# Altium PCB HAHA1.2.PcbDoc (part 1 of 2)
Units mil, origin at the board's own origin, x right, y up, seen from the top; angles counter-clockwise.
Board outline 7003.97 x 7003.97 mil, 2 copper layers (Top Layer, Bottom Layer); 140 components, 182 nets, 713 pads, 299 vias.
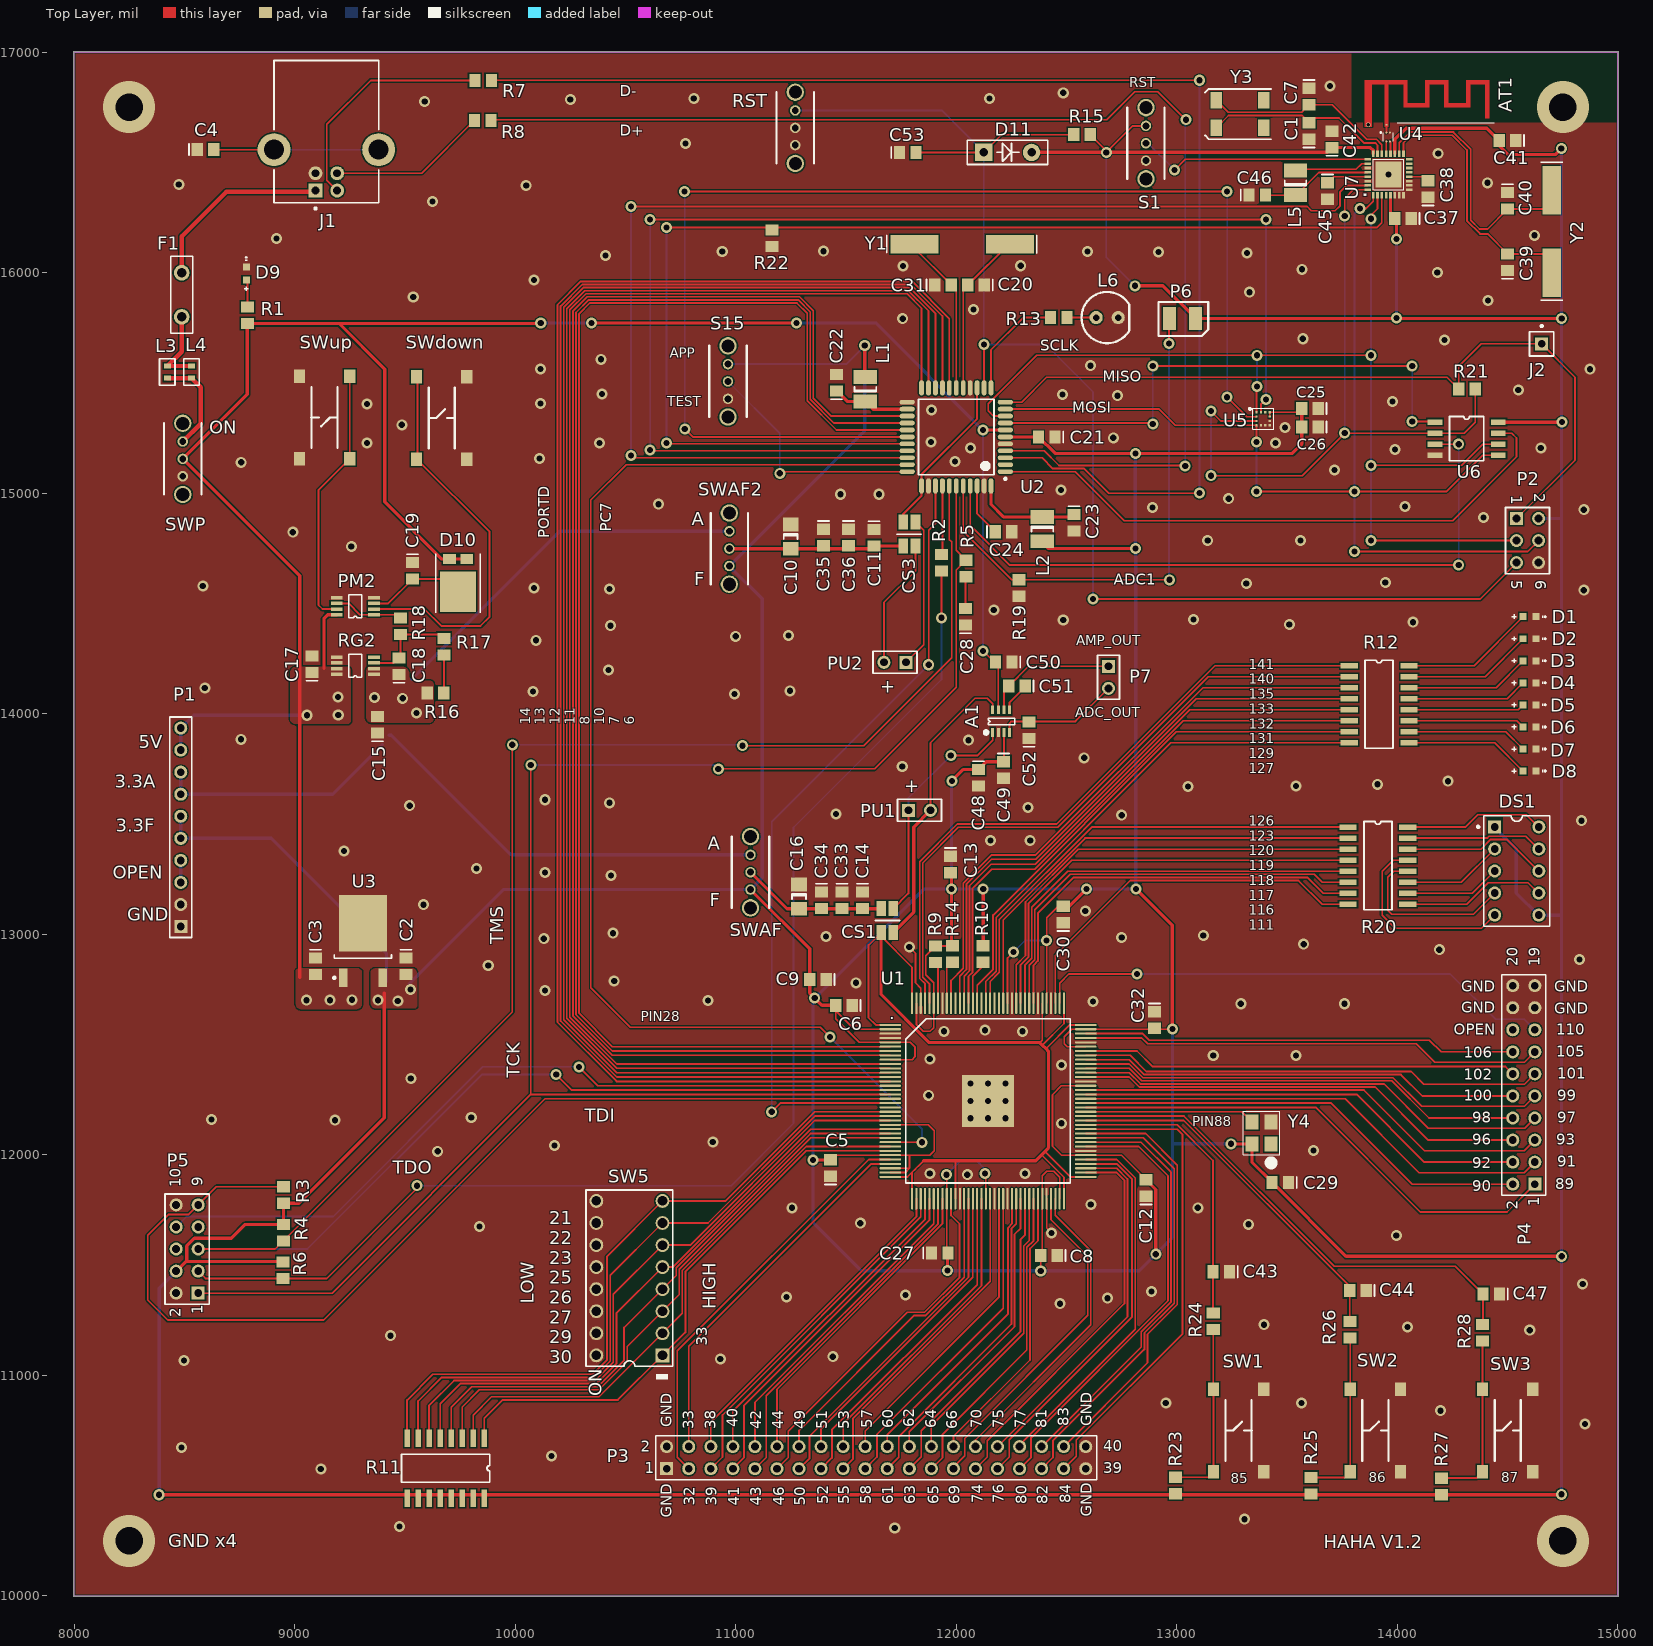
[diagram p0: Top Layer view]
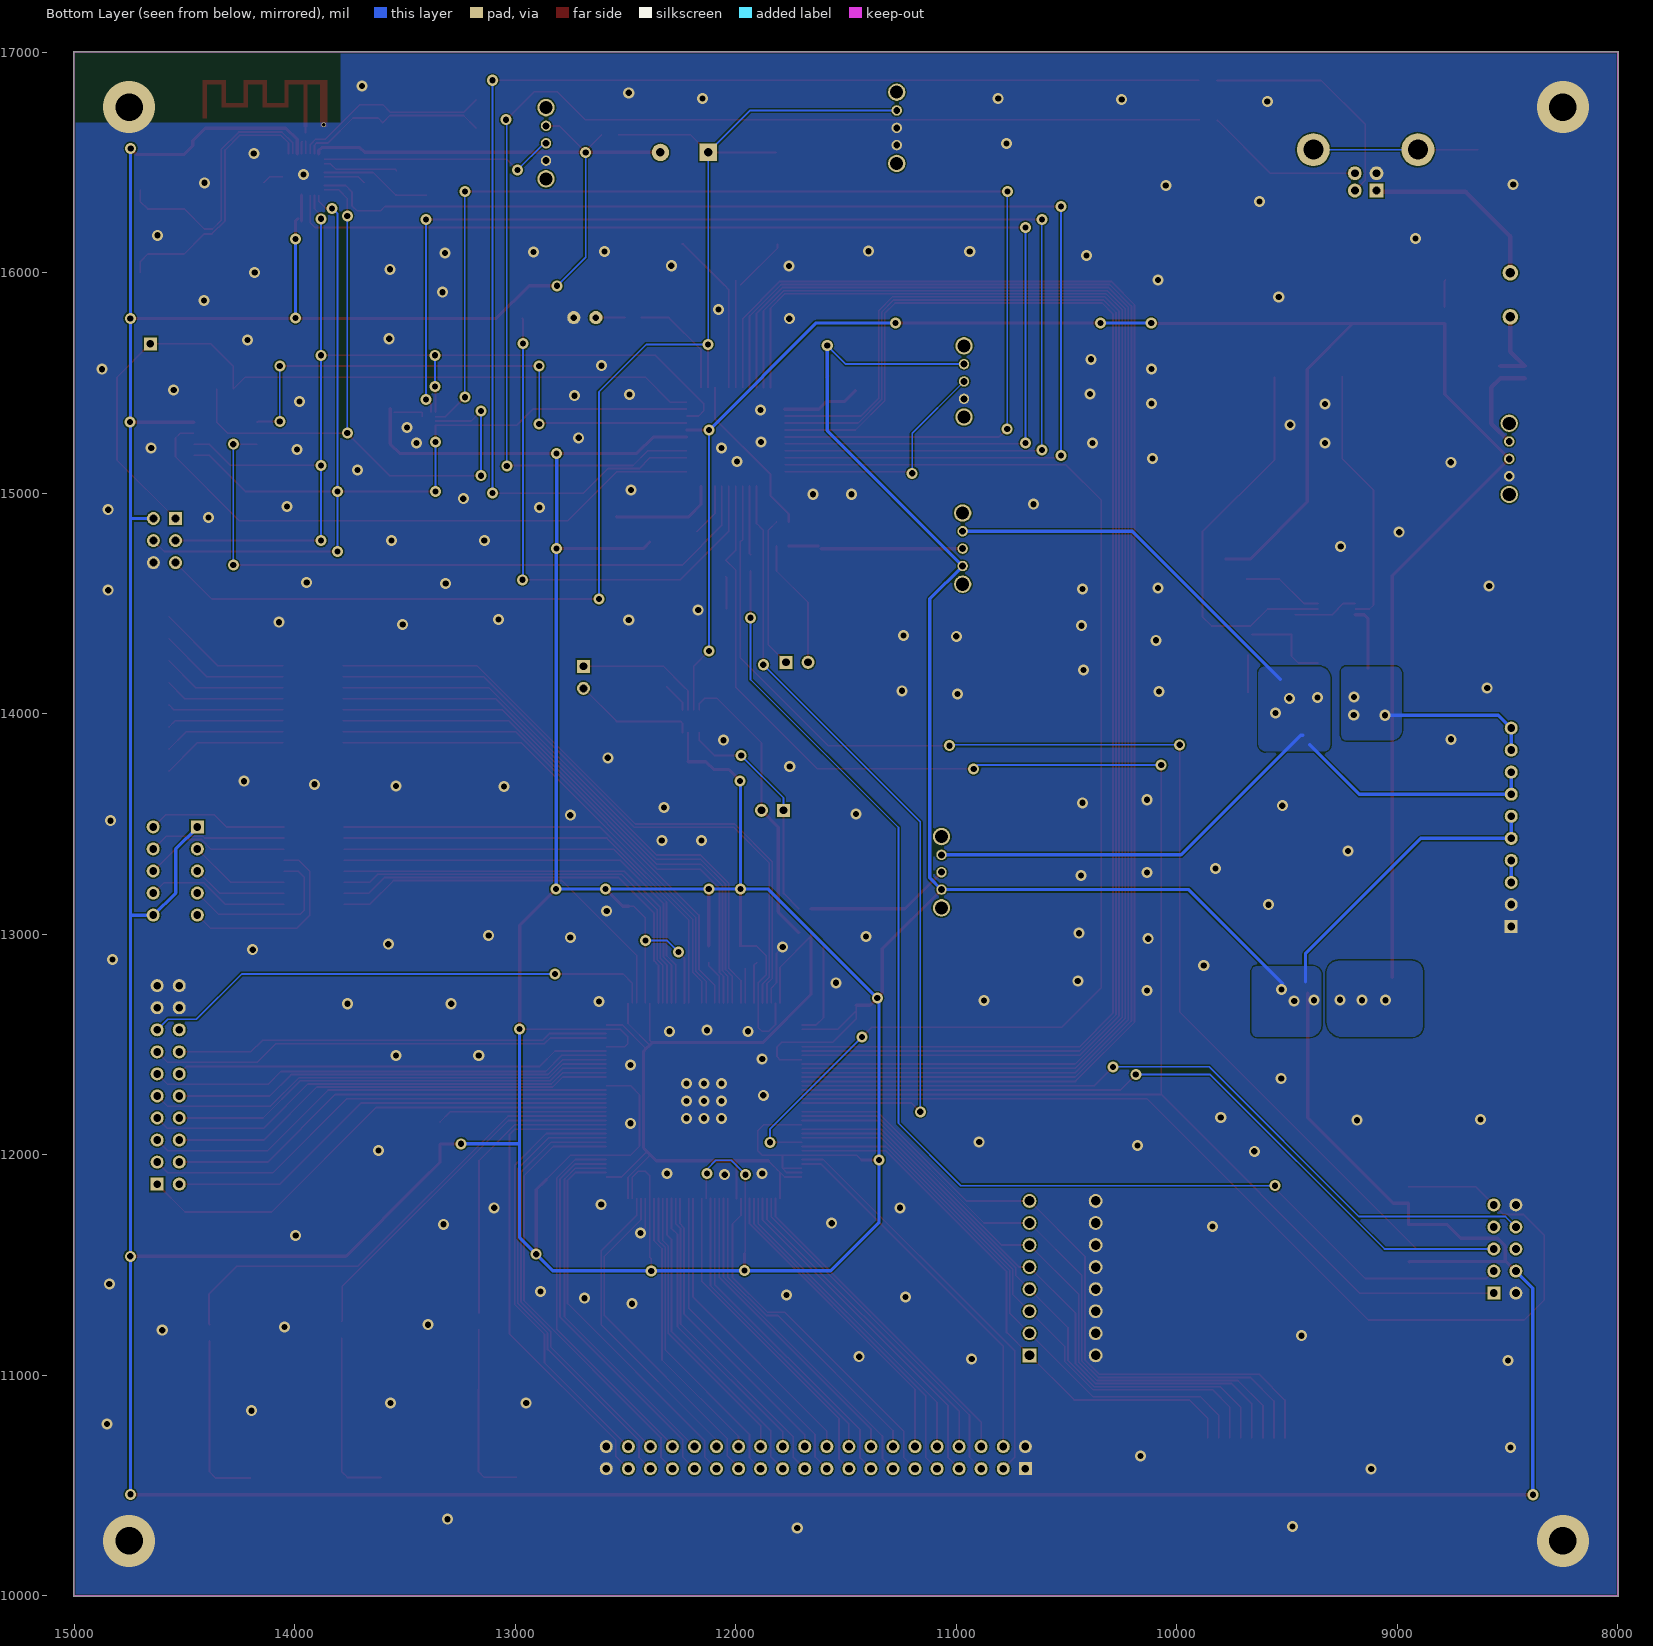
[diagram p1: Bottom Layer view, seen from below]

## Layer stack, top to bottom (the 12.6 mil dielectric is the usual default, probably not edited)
Top Solder: solder mask 0.4, Solder Resist, Dk 3.5
Top Layer: signal copper 1.4
Dielectric 1: dielectric 12.6, FR-4, Dk 4.8
Bottom Layer: signal copper 1.4
Bottom Solder: solder mask 0.4, Solder Resist, Dk 3.5

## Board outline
8000,9998.02 cw(c8000,10000) 7998.02,10000 7998.02,17000 cw(c8000,17000) 8000,17001.98 15000,17001.98 cw(c15000,17000) 15001.98,17000 15001.98,10000 cw(c15000,10000) 15000,9998.02

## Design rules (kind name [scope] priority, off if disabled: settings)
Clearance [All] p1: gap=6
HoleSize [All] p1: absolutevalues=TRUE maxlimit=125.98 minlimit=1 maxpercent=80.000 minpercent=20.000
MinimumSolderMaskSliver [All] p1 off: minsoldermaskwidth=4
PlaneConnect [All] p1: planeconnectstyle=Direct reliefexpansion=20 reliefentries=4 reliefconductorwidth=10 reliefairgap=10
PolygonConnect [All] p1: connectstyle=Direct reliefconductorwidth=10 reliefentries=4 polygonreliefangle="90 Angle" airgapwidth=10
RoutingVias [All] p1: holewidth=28 width=50 viastyle="Through Hole" minholewidth=28 minwidth=50 maxholewidth=28 maxwidth=50
SilkToSilkClearance [All] p1: silktosilkclearance=6
SilkToSolderMaskClearance [IsPad] p1: minsilkscreentomaskgap=7.8 clearancetoexposedcopper=TRUE
SolderMaskExpansion [All] p1: expansion=4
Width [All] p1: maxlimit=20 minlimit=6 preferedwidth=10
25 further rules are at their usual default settings.

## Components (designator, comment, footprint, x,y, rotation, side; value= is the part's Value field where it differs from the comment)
A1 "AD8293G80" SOP8_amp 12165,13915 r90 top
AT1 "AT" AT 13850,16680 r0 top
C1 "12pF" 0805 13600,16642.4 r90 top
C2 "2.2uF" 0805 9505,12855 r270 top
C3 "0.1uF" 0805 9095,12855 r270 top
C4 "0.1uF" 0805 8596,16557 r0 top
C5 "0.1uF" 0805 11430,11940 r90 top
C6 "0.1uF" 0805 11491,12678 r180 top
C7 "12pF" 0805 13599,16798 r270 top
C8 "0.1uF" 0805 12420,11543 r180 top
C9 "10uF" 0805 11373,12795 r180 top
C10 "100uF" 1206 11249,14803 r270 top
C11 "0.01uF" 0805 11626,14798 r270 top
C12 "0.1uF" 0805 12860,11850 r90 top
C13 "0.1uF" 0805 11974,13316 r270 top
C14 "0.01uF" 0805 11574,13154 r270 top
C15 "1uF" 0805 9375.97,13950 r90 top
C16 "100uF" 1206 11287,13171 r270 top
C17 "1uF" 0805 9079.97,14224 r90 top
C18 "100pF" 0805 9473,14215 r90 top
C19 "10uF" 0805 9534.97,14648 r270 top
C20 "20pF" 0805 12090,15944 r180 top
C21 "1uF" 0805 12410,15255 r180 top
C22 "0.1uF" 0805 11458,15501 r90 top
C23 "0.1uF" 0805 12533,14866 r270 top
C24 "0.1uF" 0805 12214,14825 r0 top
C25 "0.1uF" 0805 13604,15383 r180 top
C26 "10uF" 0805 13604,15299 r180 top
C27 "0.1uF" 0805 11925,11555 r0 top
C28 "100pF" 0805 12042,14440 r90 top
C29 "0.01uF" 0805 13469,11875 r180 top
C30 "0.1uF" 0805 12485,13090 r90 top
C31 "20pF" 0805 11940,15944 r0 top
C32 "0.1uF" 0805 12899,12611 r270 top
C33 "0.1uF" 0805 11481,13154 r270 top
C34 "10uF" 0805 11389,13154 r270 top
C35 "10uF" 0805 11397,14799 r270 top
C36 "0.1uF" 0805 11512,14799 r270 top
C37 "0.1uF" 0805 14025,16245 r180 top
C38 "0.1uF" 0805 14139,16379 r90 top
C39 "18pF" 0805 14500,16047 r90 top
C40 "18pF" 0805 14500,16326 r270 top
C41 "0.1uF" 0805 14499,16598 r180 top
C42 "0.1uF" 0805 13704,16604 r90 top
C43 "0.1uF" 0805 13201,11470 r180 top
C44 "0.1uF" 0805 13821,11384 r180 top
C45 "0.1uF" 0805 13684,16370 r270 top
C46 "0.1uF" 0805 13365,16351 r0 top
C47 "0.1uF" 0805 14425,11370 r180 top
C48 "10uF" 0805 12100,13710 r270 top
C49 "0.1uF" 0805 12215,13745 r270 top
C50 "0.1uF" 0805 12215,14235 r180 top
C51 "1300pF" 0805 12275,14125 r180 top
C52 "39nF" 0805 12330,13925 r90 top
C53 "0.1uF" 0805 11780,16545 r0 top
CS1 "current_sense" Current_Sense 11659,13008 r90 top
CS3 "current_sense" Current_Sense 11815,14869 r270 top
D1 "Green" LED 14599,14440 r180 top
D2 "Green" LED 14599,14340 r180 top
D3 "Green" LED 14599,14240 r180 top
D4 "Green" LED 14599,14140 r180 top
D5 "Green" LED 14599,14040 r180 top
D6 "Green" LED 14599,13940 r180 top
D7 "Green" LED 14599,13840 r180 top
D8 "Green" LED 14599,13740 r180 top
D9 "Red" LED 8781,15996.6 r270 top
D10 "FSV8100V" FSV8100V 9740.97,14593 r90 top
D11 "1N4148" DIP2_4148 12125,16545 r0 top
DS1 "Dpy Amber-CA" DIP10_7seg 14441,13487 r0 top
F1 "500mA" fuse 8488,15799 r90 top
J1 "440119-1" 440119 9144,16411 r90 top
J2 "Header" PIN1 14654,15677 r0 top
L1 "10uH" 1210 11588,15471 r90 top
L2 "10uH" 1210 12390,14837 r270 top
L3 "bead" bead 8423,15549 r270 top
L4 "bead" bead 8533,15549 r270 top
L5 "10uH" 1210 13538,16407 r90 top
L6 "make it 5mm above the board" Led_hole 12684,15796 r0 top
P1 "Header 10" HDR1X10 8484,13035 r90 top
P2 "Header 3X2" HDR2X3 14540,14885 r270 top
P3 "Header" HDR2X20 10687,10577 r0 top
P4 "Header" HDR2X10 14623,11867 r90 top
P5 "JTAG Header" HDR2X5 8563,11373 r90 top
P6 "Photodiode" Photodiode 12967,15792 r0 top
P7 "Header" HDR1X2 12690,14215 r270 top
PM2 "100k" mSOP8 9359.97,14449 r180 top
PU1 "Header" HDR1X2 11783,13562 r0 top
PU2 "Header" HDR1X2 11772,14233 r180 top
R1 "120Ω" 6-0805 8786,15806.6 r90 top
R2 "22Ω" ERA-0805 11933,14684 r270 top
R3 "10k" 6-0805 8950,11818 r90 top
R4 "10k" 6-0805 8949,11647 r270 top
R5 "68Ω" 6-0805 12045,14659 r90 top
R6 "10k" 6-0805 8947,11477 r270 top
R7 "22Ω" ERA-0805 9855,16871 r0 top
R8 "22Ω" ERA-0805 9853,16690 r0 top
R9 "10k" 6-0805 11905,12909 r90 top
R10 "10k" 6-0805 12122,12911 r90 top
R11 "10k" SOP16 9860,10715 r270 top
R12 "47Ω" SOP16 13781,14218 r0 top
R13 "330Ω" 6-0805 12465,15796 r0 top
R14 "10k" 6-0805 11983,12910 r90 top
R15 "10k" 6-0805 12570,16625 r0 top
R16 "30k" 6-0805 9638.97,14094 r0 top
R17 "110k" 6-0805 9678,14304 r90 top
R18 "43k" 6-0805 9480,14397 r270 top
R19 "330k" 6-0805 12284,14570 r90 top
R20 "56Ω" SOP16 13776,13486 r0 top
R21 "1k" 6-0805 14315,15472 r0 top
R22 "10k" 6-0805 11164,16156 r90 top
R23 "39k" 6-0805 12994,10501 r90 top
R24 "6.8k" 6-0805 13165,11246 r90 top
R25 "39k" 6-0805 13608,10500 r90 top
R26 "6.8k" 6-0805 13786,11207 r90 top
R27 "39k" 6-0805 14200,10497 r90 top
R28 "6.8k" 6-0805 14386,11193 r90 top
RG2 "ADP3334" mSOP8 9359.97,14179 r180 top
RST "switch" ck_switch 11270,16495 r0 top
S1 "switch" ck_switch 12860,16425 r0 top
S15 "switch" ck_switch 10965,15345 r0 top
SW1 "SW_tact" SW_tact 13280,10750 r90 top
SW2 "SW_tact" SW_tact 13900,10750 r90 top
SW3 "SW_tact" SW_tact 14500,10750 r90 top
SW5 "A6H-8101" DIP16_sw 10668,11091 r180 top
SWAF "switch" ck_switch 11067,13120 r0 top
SWAF2 "switch" ck_switch 10971,14587 r0 top
SWdown "SW_tact" SW_tact 9667,15341 r90 top
SWP "switch" ck_switch 8493,14994 r0 top
SWup "SW_tact" SW_tact 9136,15343 r270 top
U1 "10M50SCE144C8G" Quad144b 11701,12589 r0 top
U2 "ATmega16U4-AU" 44ML_N 12000,15255 r180 top
U3 "LF33ABDT-TR" TO-252_N 9310,12970 r90 top
U4 "balun" Matching_C 13950,16595 r90 top
U5 "ACC" ACC 13391,15337 r0 top
U6 "25LC1024" 25LC1024 14170,15322 r0 top
U7 "BLUENRGQTR" Quad32 13890,16350 r90 top
Y1 "XTAL" SOP2 11810,16129 r0 top
Y2 "XTAL" CO 14700,16000 r90 top
Y3 "32k" SOP4 13178,16782 r0 top
Y4 "ASFL1" ASFL1 13384,12099 r90 top

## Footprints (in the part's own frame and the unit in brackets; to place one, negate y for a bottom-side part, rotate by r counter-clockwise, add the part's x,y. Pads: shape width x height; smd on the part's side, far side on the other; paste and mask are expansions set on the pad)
6-0805 [mm] "Chip Resistor; Body 2 x 1.2 mm (LxW typ)"
  rect 1.3x1.5 smd: 1(-0.95,0) 2(0.95,0)
25LC1024 [mm]
  rect 1.7x0.65 smd: 1(0,0) 2(0,-1.27) 3(0,-2.54) 4(0,-3.81) 5(7.3,-3.81) 6(7.3,-2.54) 7(7.3,-1.27) 8(7.3,0)
  silkscreen extent 1.68,-4.44 5.62,0.64
44ML_N [mm] "Thin QFP, 44-Leads, Body 10x10mm, Pitch 0.8mm, IPC Medium Density"
  oval 1.75x0.55 smd: 1(-5.65,4) 2(-5.65,3.2) 3(-5.65,2.4) 4(-5.65,1.6) 5(-5.65,0.8) 6(-5.65,0) 7(-5.65,-0.8) 8(-5.65,-1.6) 9(-5.65,-2.4) 10(-5.65,-3.2) 11(-5.65,-4) 23(5.65,-4) 24(5.65,-3.2) 25(5.65,-2.4) 26(5.65,-1.6) 27(5.65,-0.8) 28(5.65,0) 29(5.65,0.8) 30(5.65,1.6) 31(5.65,2.4) 32(5.65,3.2) 33(5.65,4)
  oval 0.55x1.75 smd: 12(-4,-5.65) 13(-3.2,-5.65) 14(-2.4,-5.65) 15(-1.6,-5.65) 16(-0.8,-5.65) 17(0,-5.65) 18(0.8,-5.65) 19(1.6,-5.65) 20(2.4,-5.65) 21(3.2,-5.65) 22(4,-5.65) 34(4,5.65) 35(3.2,5.65) 36(2.4,5.65) 37(1.6,5.65) 38(0.8,5.65) 39(0,5.65) 40(-0.8,5.65) 41(-1.6,5.65) 42(-2.4,5.65) 43(-3.2,5.65) 44(-4,5.65)
  silkscreen extent -5.77,-4.35 4.35,4.95, body extent -5,-5 5,5, height 1.2
0805 [mm] "Chip Capacitor; Body 2.0 x 1.2 mm (LxW typ)"
  rect 1.3x1.5 smd: 1(-0.95,0) 2(0.95,0)
  silkscreen extent -1.9,-0.65 -1.9,0.65
1206 [mm] "Chip Capacitor; Body 3.2 x 1.6 mm (LxW typ)"
  rect 1.6x1.8 smd: 1(-1.4,0) 2(1.4,0)
  silkscreen extent -0.3,-0.8 0.3,0.8
1210 [mm] "Chip Capacitor; Body 3.2 x 2.5 mm (LxW typ)"
  rect 1.6x2.7 smd: 1(-1.4,0) 2(1.4,0)
  silkscreen extent -0.3,-1.25 0.3,1.25
440119 [mm] "Connector; USB1.1, Type B, Thru-Hole; 4 Position; Right Angle"
  rect 1.6x1.6 hole 0.92: 1(-1,1.25)
  round 1.6 hole 0.92: 2(-1,-1.25) 3(1,-1.25) 4(1,1.25)
  round 3.8 hole 2.3: 5(3.71,6.02) 6(3.71,-6.02)
  silkscreen extent -3.18,-6.02 13.99,6.02
ACC [mm]
  rect 0.276x0.25 smd: 1(-0.763,0.75) 2(-0.763,0.25) 3(-0.763,-0.25) 4(-0.763,-0.75) 10(0.763,0.75)
  rect 0.25x0.275 smd: 5(-0.25,-0.75) 6(0.25,-0.75) 11(0.25,0.75) 12(-0.25,0.75)
  rect 0.275x0.25 smd: 7(0.763,-0.75) 8(0.763,-0.25) 9(0.763,0.25)
  silkscreen extent -1.62,-1.2 1.2,1.24
ASFL1 [mm]
  rect 1.7x1.5 smd: 1(-1.27,-1.1) 2(1.27,-1.1) 3(1.27,1.1) 4(-1.27,1.1)
  silkscreen extent -3.68,-2.1 2.5,2.1
AT [mil]
  round 22 hole 15: 1(17.72,-9.84)
  rect 7.87x7.87 smd: 1(100,-10)
  Top Layer region: 90.55,-19.69 110.24,-19.69 110.24,177.17 90.55,177.17
  Top Layer region: 547.24,18.11 566.93,18.11 566.93,177.17 547.24,177.17
  Top Layer region: 460.63,173.23 566.93,173.23 566.93,192.91 460.63,192.91
  Top Layer region: 460.63,69.29 480.32,69.29 480.32,177.17 460.63,177.17
  Top Layer region: 377.95,69.29 468.5,69.29 468.5,88.98 377.95,88.98
  Top Layer region: 362.2,69.29 381.89,69.29 381.89,177.17 362.2,177.17
  Top Layer region: 275.59,173.23 381.89,173.23 381.89,192.91 275.59,192.91
  Top Layer region: 275.59,69.29 295.28,69.29 295.28,177.17 275.59,177.17
  Top Layer region: 192.91,69.29 279.53,69.29 279.53,88.98 192.91,88.98
  Top Layer region: 177.17,69.29 196.85,69.29 196.85,177.17 177.17,177.17
  Top Layer region: 0,173.23 196.85,173.23 196.85,192.91 0,192.91
  Top Layer region: 0,-19.69 35.43,-19.69 35.43,177.17 0,177.17
  silkscreen extent 150,0 590,0
bead [mm]
  rect 0.6x0.8 smd: 0(-0.7,0) 1(0.7,0)
  silkscreen extent -1.52,-0.89 1.52,0.89
ck_switch [mm]
  round 1.2 hole 0.8: 1(0,2.1) 2(0,4.1) 3(0,6.1)
  round 2 hole 1.5: ""(0,0) ""(0,8.2)
  silkscreen extent -2.15,0 2.15,8.2
CO [mm]
  rect 5.6x2.1 smd: 1(0,0) 2(9.5,0)
  silkscreen extent -3.17,-1.27 12.7,1.27
Current_Sense [mm]
  rect 1.75x1.1 smd: 1(0,0) 2(2.75,0) 3(0,-1.4) 4(2.75,-1.4)
  silkscreen extent 1.4,-2.16 1.4,0.64
DIP2_4148 [mm]
  rect 2x2 hole 1: 1(0,0)
  round 2 hole 1: 2(5.5,0)
  silkscreen extent -1.91,-1.4 7.37,1.4
DIP10_7seg [mm]
  rect 1.5x1.5 hole 0.9: 1(0,0)
  round 1.5 hole 0.9: 2(0,-2.54) 3(0,-5.08) 4(0,-7.62) 5(0,-10.16) 6(5.08,-10.16) 7(5.08,-7.62) 8(5.08,-5.08) 9(5.08,-2.54) 10(5.08,0)
  silkscreen extent -2.03,-11.43 6.35,1.27
DIP16_sw [mm]
  rect 1.6x1.6 hole 1.1: 1(0,0)
  round 1.6 hole 1.1: 2(0,-2.54) 3(0,-5.08) 4(0,-7.62) 5(0,-10.16) 6(0,-12.7) 7(0,-15.24) 8(0,-17.78) 9(7.62,-17.78) 10(7.62,-15.24) 11(7.62,-12.7) 12(7.62,-10.16) 13(7.62,-7.62) 14(7.62,-5.08) 15(7.62,-2.54) 16(7.62,0)
  silkscreen extent -1.19,-19.05 8.81,2.79
ERA-0805 [mm] "Chip Resistor; Body 2 x 1.3 mm (LxW typ)"
  rect 1.3x1.5 smd: 1(-0.95,0) 2(0.95,0)
FSV8100V [mm] "Diode"
  rect 1.15x1.45 smd: 1(2.75,0.985) 2(2.75,-0.985)
  rect 4.65x4.15 smd: 3(-1,0)
  silkscreen extent -3.43,-2.54 3.37,2.54
fuse [mm]
  round 1.8 hole 1.1: 1(0,0) 2(5.08,0)
  silkscreen extent -1.91,-1.27 6.98,1.27
HDR1X2 [mm] "Connector; Header; 2 Position"
  rect 1.5x1.5 hole 0.9: 1(0,0)
  round 1.5 hole 0.9: 2(2.54,0)
  silkscreen extent -1.27,-1.27 3.81,1.27
HDR1X10 [mm] "Connector; Header; 10 Position"
  rect 1.5x1.5 hole 0.9: 1(0,0)
  round 1.5 hole 0.9: 2(2.54,0) 3(5.08,0) 4(7.62,0) 5(10.16,0) 6(12.7,0) 7(15.24,0) 8(17.78,0) 9(20.32,0) 10(22.86,0)
  silkscreen extent -1.27,-1.27 24.13,1.27
HDR2X3 [mm] "Connector; Header; 3x2 Position"
  rect 1.5x1.5 hole 0.9: 1(0,0)
  round 1.5 hole 0.9: 2(0,2.54) 3(2.54,0) 4(2.54,2.54) 5(5.08,0) 6(5.08,2.54)
  silkscreen extent -1.27,-1.27 6.35,3.81
HDR2X5 [mm] "Connector; Header; 5x2 Position"
  rect 1.5x1.5 hole 0.9: 1(0,0)
  round 1.5 hole 0.9: 2(0,2.54) 3(2.54,0) 4(2.54,2.54) 5(5.08,0) 6(5.08,2.54) 7(7.62,0) 8(7.62,2.54) 9(10.16,0) 10(10.16,2.54)
  silkscreen extent -1.27,-1.27 11.43,3.81
HDR2X10 [mm] "Connector; Header; 10x2 Position"
  rect 1.5x1.5 hole 0.9: 1(0,0)
  round 1.5 hole 0.9: 2(0,2.54) 3(2.54,0) 4(2.54,2.54) 5(5.08,0) 6(5.08,2.54) 7(7.62,0) 8(7.62,2.54) 9(10.16,0) 10(10.16,2.54) 11(12.7,0) 12(12.7,2.54) 13(15.24,0) 14(15.24,2.54) 15(17.78,0) 16(17.78,2.54) 17(20.32,0) 18(20.32,2.54) 19(22.86,0) 20(22.86,2.54)
  silkscreen extent -1.27,-1.27 24.13,3.81
HDR2X20 [mm] "Connector; Header; 20x2 Position"
  rect 1.5x1.5 hole 0.9: 1(0,0)
  round 1.5 hole 0.9: 2(0,2.54) 3(2.54,0) 4(2.54,2.54) 5(5.08,0) 6(5.08,2.54) 7(7.62,0) 8(7.62,2.54) 9(10.16,0) 10(10.16,2.54) 11(12.7,0) 12(12.7,2.54) 13(15.24,0) 14(15.24,2.54) 15(17.78,0) 16(17.78,2.54) 17(20.32,0) 18(20.32,2.54) 19(22.86,0) 20(22.86,2.54) 21(25.4,0) 22(25.4,2.54) 23(27.94,0) 24(27.94,2.54) 25(30.48,0) 26(30.48,2.54) 27(33.02,0) 28(33.02,2.54) 29(35.56,0) 30(35.56,2.54) 31(38.1,0) 32(38.1,2.54) 33(40.64,0) 34(40.64,2.54) 35(43.18,0) 36(43.18,2.54) 37(45.72,0) 38(45.72,2.54) 39(48.26,0) 40(48.26,2.54)
  silkscreen extent -1.27,-1.27 49.53,3.81
LED [mm]
  rect 0.8x0.8 smd: 1(0.75,0) 2(-0.75,0)
  silkscreen extent -1.91,-0.25 2.03,0.25
Led_hole [mil]
  round 60 hole 29.53: 0(50,0) 1(-50,0)
  silkscreen extent -116,-116 101,116
Matching_C [mm]
  round 0.22 smd mask+0.05: A1(1,0) A2(1,-0.4) B1(0,0) B2(0,-0.4)
  silkscreen extent 0,-0.78 1.04,0.66
mSOP8 [mm]
  rect 1.35x0.4 smd: 1(0,0) 2(0,-0.65) 3(0,-1.3) 4(0,-1.95) 5(4.3,-1.95) 6(4.3,-1.3) 7(4.3,-0.65) 8(4.3,0)
  silkscreen extent 1.41,-2.28 2.89,0.33
Photodiode [mm]
  rect 1.5x2.6 smd: 0(3,0) 1(0,0)
  silkscreen extent -1.27,-2.03 4.44,1.91
PIN1 [mm] "Connector; Plug"
  rect 1.5x1.5 hole 0.9: 1(0,0)
  silkscreen extent -1.4,-1.4 1.4,2.17
Quad32 [mm]
  rect 3x3 smd: 0(2.413,-1.75)
  rect 0.75x0.3 smd: 1(0,0) 2(0,-0.5) 3(0,-1) 4(0,-1.5) 5(0,-2) 6(0,-2.5) 7(0,-3) 8(0,-3.5) 17(4.8,-3.5) 18(4.8,-3) 19(4.8,-2.5) 20(4.8,-2) 21(4.8,-1.5) 22(4.8,-1) 23(4.8,-0.5) 24(4.8,0)
  rect 0.3x0.75 smd: 9(0.65,-4.15) 10(1.15,-4.15) 11(1.65,-4.15) 12(2.15,-4.15) 13(2.65,-4.15) 14(3.15,-4.15) 15(3.65,-4.15) 16(4.15,-4.15) 25(4.15,0.65) 26(3.65,0.65) 27(3.15,0.65) 28(2.65,0.65) 29(2.15,0.65) 30(1.65,0.65) 31(1.15,0.65) 32(0.65,0.65)
  silkscreen extent 0.64,-3.51 4.17,0
Quad144b [mm]
  oval 2.5x0.24 smd: 1(0,0) 2(0,-0.5) 3(0,-1) 4(0,-1.5) 5(0,-2) 6(0,-2.5) 7(0,-3) 8(0,-3.5) 9(0,-4) 10(0,-4.5) 11(0,-5) 12(0,-5.5) 13(0,-6) 14(0,-6.5) 15(0,-7) 16(0,-7.5) 17(0,-8) 18(0,-8.5) 19(0,-9) 20(0,-9.5) 21(0,-10) 22(0,-10.5) 23(0,-11) 24(0,-11.5) 25(0,-12) 26(0,-12.5) 27(0,-13) 28(0,-13.5) 29(0,-14) 30(0,-14.5) 31(0,-15) 32(0,-15.5) 33(0,-16) 34(0,-16.5) 35(0,-17) 36(0,-17.5) 73(22.5,-17.5) 74(22.5,-17) 75(22.5,-16.5) 76(22.5,-16) 77(22.5,-15.5) 78(22.5,-15) 79(22.5,-14.5) 80(22.5,-14) 81(22.5,-13.5) 82(22.5,-13) 83(22.5,-12.5) 84(22.5,-12) 85(22.5,-11.5) 86(22.5,-11) 87(22.5,-10.5) 88(22.5,-10) 89(22.5,-9.5) 90(22.5,-9) 91(22.5,-8.5) 92(22.5,-8) 93(22.5,-7.5) 94(22.5,-7) 95(22.5,-6.5) 96(22.5,-6) 97(22.5,-5.5) 98(22.5,-5) 99(22.5,-4.5) 100(22.5,-4) 101(22.5,-3.5) 102(22.5,-3) 103(22.5,-2.5) 104(22.5,-2) 105(22.5,-1.5) 106(22.5,-1) 107(22.5,-0.5) 108(22.5,0)
  oval 0.24x2.5 smd: 37(2.5,-20) 38(3,-20) 39(3.5,-20) 40(4,-20) 41(4.5,-20) 42(5,-20) 43(5.5,-20) 44(6,-20) 45(6.5,-20) 46(7,-20) 47(7.5,-20) 48(8,-20) 49(8.5,-20) 50(9,-20) 51(9.5,-20) 52(10,-20) 53(10.5,-20) 54(11,-20) 55(11.5,-20) 56(12,-20) 57(12.5,-20) 58(13,-20) 59(13.5,-20) 60(14,-20) 61(14.5,-20) 62(15,-20) 63(15.5,-20) 64(16,-20) 65(16.5,-20) 66(17,-20) 67(17.5,-20) 68(18,-20) 69(18.5,-20) 70(19,-20) 71(19.5,-20) 72(20,-20) 109(20,2.5) 110(19.5,2.5) 111(19,2.5) 112(18.5,2.5) 113(18,2.5) 114(17.5,2.5) 115(17,2.5) 116(16.5,2.5) 117(16,2.5) 118(15.5,2.5) 119(15,2.5) 120(14.5,2.5) 121(14,2.5) 122(13.5,2.5) 123(13,2.5) 124(12.5,2.5) 125(12,2.5) 126(11.5,2.5) 127(11,2.5) 128(10.5,2.5) 129(10,2.5) 130(9.5,2.5) 131(9,2.5) 132(8.5,2.5) 133(8,2.5) 134(7.5,2.5) 135(7,2.5) 136(6.5,2.5) 137(6,2.5) 138(5.5,2.5) 139(5,2.5) 140(4.5,2.5) 141(4,2.5) 142(3.5,2.5) 143(3,2.5) 144(2.5,2.5)
  rect 6x6 smd: 145(11.25,-8.75)
  silkscreen extent 1.79,-18.21 20.71,0.71
SOP2 [mm]
  rect 5.5x2.1 smd: 1(0,0) 2(11,0)
  silkscreen extent -3.17,-1.02 14.1,1
SOP4 [mm]
  rect 1.3x1.9 smd: 1(0,-3.2) 2(5.5,-3.2) 3(5.5,0) 4(0,0)
  silkscreen extent -1.27,-4.5 6.35,1.27
SOP8_amp [mm]
  rect 1x0.35 smd: 1(0,0) 2(0,-0.65) 3(0,-1.3) 4(0,-1.95) 5(2.6,-1.95) 6(2.6,-1.3) 7(2.6,-0.65) 8(2.6,0)
  silkscreen extent -0.18,-2.54 1.65,0.94
SOP16 [mm]
  rect 2x0.63 smd: 1(0,0) 2(0,-1.27) 3(0,-2.54) 4(0,-3.81) 5(0,-5.08) 6(0,-6.35) 7(0,-7.62) 8(0,-8.89) 9(6.9,-8.89) 10(6.9,-7.62) 11(6.9,-6.35) 12(6.9,-5.08) 13(6.9,-3.81) 14(6.9,-2.54) 15(6.9,-1.27) 16(6.9,0)
  silkscreen extent 1.84,-9.53 5.06,0.64
SW_tact [mm]
  rect 1.55x1.3 smd: 1(-4.75,2.9) 2(4.75,2.9) 3(-4.75,-2.9) 4(4.75,-2.9)
  silkscreen extent -3.5,-1.52 3.5,1.5
TO-252_N [mm] "D-PAK, 4-Leads, Body 6.1x6.5mm, Pitch 2.28mm, Lead Span 9.7mm, IPC Medium Density"
  rect 2.1x0.95 smd: 1(-4.25,2.28) 3(-4.25,-2.28)
  rect 6.5x5.5 smd: 4(2.05,0)
  silkscreen extent -4.37,-3.3 -1.6,3.43, body extent -2,-3.3 4.2,3.3, height 2.4

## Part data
C1 C2 C3 C4 C5 C6 C7 C8 C9 C11 C12 C13 C14 C15 C17 C18 C19 C20 C21 C22 C23 C24 C25 C26 C27 C28 C29 C30 C31 C32 C33 C34 C35 C36 C37 C38 C39 C40 C41 C42 C43 C44 C45 C46 C47 C48 C49 C50 C51 C52 C53: library part C0805, "Ceramic Chip Capacitor - Standard"
C10 C16: library part C1206, "Ceramic Chip Capacitor - Standard"
D1 D2 D3 D4 D5 D6 D7 D8 D9: library part LED3, "Typical BLUE SiC LED"
DS1: "7.62 mm Black Surface Orange 7-Segment Display: CA, RH DP"
F1: library part "Fuse 2", "Fuse"
J1: "USB 1.1, Right Angle, Thru-Hole, B Type, Receptacle, 4 Position, Beige"
J2: library part Socket
L1 L2 L5: library part inductor
L6: library part Led_hole
P1: "Header, 10-Pin"
P2: "Header, 3-Pin, Dual row"
P3: library part "Header 20X2"
P4: library part "Header 10X2"
P5: library part "Header 5X2", "Header, 5-Pin, Dual row"
P7 PU1 PU2: library part "Header 2"
PM2: library part DS1809
R1 R5 R13 R18 R19: library part ERJ6EN, "Precision Thick Film Chip Resistor, 10 Ohm to 2.2M Ohm Range, 1% Tolerance, 0805 Size, 0.1 W"
R2 R7 R8: library part ERA6Y, "Rectangular Thick Film Chip Resistor, 10 Ohm to 1M Ohm Range, 0.1% and 0.5% Tolerance, 0805 Size, 0.1 W"
R3 R4 R6 R9 R10 R14 R15 R16 R17 R21 R22 R23 R24 R25 R26 R27 R28: library part ERJ6GE, "Thick Film Chip Resistor, 1 Ohm to 10M Ohm Range, 5% Tolerance, 0805 Size, 0.125 W"
R11 R12 R20: library part "Res Pack3", "Isolated Resistor Network"
RST S1 S15 SWAF SWAF2 SWP: library part ck_switch
SW5: "Ultra-Low Profile, Half-Pitch, SM, Slide DIP Switch, Flat Actuator, White Striker, 8 Position, SPST, Std. Model"
U2: "8-bit AVR Microcontroller, 2.7-5.5V, 16KB Flash, 1.25KB EEPROM, 512 Bytes SRAM, USB Controller, 44-pin TQFP, Industrial Grade (-40°C to 85°C)"
U3: "500mA, Very Low Drop (0.45V) Voltage Regulator, 3.3V, 3-Pin DPAK, Tape and Reel"
Y1 Y2: "Crystal Oscillator"

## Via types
v1: diameter 50, hole 28, Top Layer to Bottom Layer, 295 vias
v2: diameter 236.22, hole 125.98, Top Layer to Bottom Layer, 4 vias

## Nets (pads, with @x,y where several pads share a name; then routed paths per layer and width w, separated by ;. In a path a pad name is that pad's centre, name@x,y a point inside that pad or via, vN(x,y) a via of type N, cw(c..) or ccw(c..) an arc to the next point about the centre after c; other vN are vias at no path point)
A_OUT: A1.6 C51.2 P7.1 | length 606.2
  Top Layer w8: A1.6@12216.18,14017.36 12216.18,14103.58 C51.2@12237.6,14125 12327.6,14215 P7.1@12690,14215
ACC_CS: U2.28 U5.2 | length 5666
  Top Layer w8: v1(10768,16368) v1(13228,16368) ; v1(10769,15291) 10805,15255 U2.28@11777.56,15255 ; v1(13228,15435) 13316.16,15346.84 U5.2@13360.96,15346.84
  Bottom Layer w8: v1(10768,16368) 10769,16349 v1(10769,15291) ; v1(13228,15435) v1(13228,16368) v1@13228,16371
ADC_OUT: A1.4 C52.2 P7.2 | length 555.5
  Top Layer w8: A1.4@12241.77,13915 12241.77,13956.77 12250,13965 12540,13965 P7.2@12690,14115
BLUE_CS: U2.31 U7.31 | length 5818.8
  Top Layer w8: v1(10525,15170) 10534.49,15160.51 U2.31@11777.56,15160.51 ; v1(10525,16300) 13590,16300 13610,16280 13717,16280 13740,16303 13740,16366 13769.28,16395.28 U7.31@13864.41,16395.28
  Bottom Layer w8: v1(10525,15170) v1(10525,16300)
BLUE_IRQ: R22.2 U2.29 U7.3 | length 5448.6
  Top Layer w8: v1(10686,15228) 10686,15224 10686.5,15223.5 U2.29@11777.56,15223.5 ; v1(10686,16205) 13908,16205 13929.37,16226.37 U7.3@13929.37,16350
  Bottom Layer w8: v1(10686,15228) v1(10686,16205)
BLUE_RST: S1.2 U7.25 | length 1074.7
  Top Layer w8: v1(12990,16465) 13038.39,16513.39 U7.25@13864.41,16513.39
  Bottom Layer w8: S1.2@12860,16586.42 12868.58,16586.42 v1(12990,16465)
BT1: C43.2 R24.2 U1.85 | length 1335.3
  Top Layer w8: U1.85@12586.83,12136.25 13001.55,12136.25 13163.6,11974.2 C43.2@13163.6,11470 13163.6,11284.8 R24.2@13165,11283.4
BT2: C44.2 R26.2 U1.86 | length 1668.5
  Top Layer w8: U1.86@12586.83,12155.93 13031.07,12155.93 13783.6,11403.4 C44.2@13783.6,11384 13783.6,11246.8 R26.2@13786,11244.4
BT3: C47.2 R28.2 U1.87 | length 2274.7
  Top Layer w8: U1.87@12586.83,12175.61 13032.39,12175.61 13713,11495 14262.6,11495 C47.2@14387.6,11370 14387.6,11232 R28.2@14386,11230.4
C_H: A1.1 CS1.4 PU1.1 | length 1055.8
  Top Layer w8: CS1.4@11714.12,13116.27 11783,13185.15 PU1.1@11783,13562 ; v1(11975,13810) 12095,13810 12165,13880 A1.1@12165,13915
  Bottom Layer w8: PU1.1@11783,13562 11783,13618 v1(11975,13810)
C_L: A1.8 CS1.3 PU1.2 | length 1333.6
  Top Layer w8: PU1.2@11883,13562 11883,13868 12085,14070 12140,14070 12165,14045 A1.8@12165,14017.36
  Top Layer w15: CS1.3@11714.12,13008 11807,13100.88 11807,13486 PU1.2@11883,13562
CLK50: U1.88 Y4.3 | length 773
  Top Layer w8: U1.88@12586.83,12195.3 13294.39,12195.3 Y4.3@13340.69,12149
CLKOUT: U1.28 U2.32 | length 5682.7
  Top Layer w8: v1(11427,12535) 11384,12578 10522,12578 10343,12757 10343,14969 10503.02,15129.02 U2.32@11777.56,15129.02 ; U1.28@11701,12057.5 11701.5,12057 v1(11844,12057)
  Bottom Layer w8: v1(11427,12535) 11844,12118 v1(11844,12057)
CM0: U1.14 U2.18 | length 7077.2
  Top Layer w8: U1.14@11701,12333.09 10460,12333.09 10192,12601.09 10192,15854 10298,15960 11800,15960 11968.5,15791.5 U2.18@11968.5,15477.44
CM1: U1.13 U2.19 | length 6998
  Top Layer w8: U1.13@11701,12352.78 10460.11,12352.78 10206,12606.89 10206,15848.2 10303.8,15946 11794.2,15946 11937.01,15803.19 U2.19@11937.01,15477.44
CM2: U1.12 U2.20 | length 6918.8
  Top Layer w8: U1.12@11701,12372.47 10460.23,12372.47 10220,12612.69 10220,15842.4 10309.6,15932 11788.4,15932 11905.51,15814.89 U2.20@11905.51,15477.44
CM3: U1.11 U2.21 | length 6839.6
  Top Layer w8: U1.11@11701,12392.15 10460.34,12392.15 10234,12618.49 10234,15836.6 10315.4,15918 11782.6,15918 11874.02,15826.59 U2.21@11874.02,15477.44
CM4: U1.8 U2.25 | length 6706.4
  Top Layer w8: U1.8@11701,12451.2 10440.88,12451.2 10262,12630.09 10262,15825.01 10326.99,15890 11289,15890 11352,15827 11352,15431 11433.51,15349.49 U2.25@11777.56,15349.49
CM5: U1.10 U2.22 | length 6760.4
  Top Layer w8: U1.10@11701,12411.83 10460.46,12411.83 10248,12624.29 10248,15830.8 10321.2,15904 11776.8,15904 11842.52,15838.28 U2.22@11842.52,15477.44
CM6: U1.7 U2.26 | length 6664.9
  Top Layer w8: U1.7@11701,12470.89 10441,12470.89 10276,12635.89 10276,15819.21 10332.79,15876 11283.2,15876 11338,15821.2 11338,15425.2 11445.21,15317.99 U2.26@11777.56,15317.99
CM7: U1.6 U2.27 | length 6623.4
  Top Layer w8: U1.6@11701,12490.58 10441.11,12490.58 10290,12641.69 10290,15813.41 10338.59,15862 11277.4,15862 11324,15815.4 11324,15419.4 11456.91,15286.5 U2.27@11777.56,15286.5
D11: R20.1 U1.126 | length 2151.2
  Top Layer w8: U1.126@12153.76,12687.43 12153.76,12785.83 12195,12827.08 12195,13067 12614,13486 R20.1@13776,13486
D12: R20.2 U1.123 | length 2094.3
  Top Layer w8: U1.123@12212.81,12687.43 12212.81,13064.81 12584,13436 R20.2@13776,13436
D13: R20.3 U1.120 | length 2037.6
  Top Layer w8: U1.120@12271.87,12687.43 12271.87,12861.66 12314,12903.8 12314,13146.2 12553.8,13386 R20.3@13776,13386
D14: R20.4 U1.119 | length 1997.1
  Top Layer w8: U1.119@12291.55,12687.43 12291.55,12861.55 12328,12898 12328,13140.4 12523.6,13336 R20.4@13776,13336
D15: R20.5 U1.118 | length 1949.2
  Top Layer w8: U1.118@12311.24,12687.43 12311.24,12860.23 12342,12890.99 12342,13122 12506,13286 R20.5@13776,13286
D16: R20.6 U1.117 | length 1935.6
  Top Layer w8: U1.117@12330.92,12687.43 12330.92,12860.11 12356,12885.19 12356,13111 12517,13272 13623,13272 13659,13236 R20.6@13776,13236
D17: R20.7 U1.116 | length 2028.3
  Top Layer w8: U1.116@12350.61,12687.43 12350.61,12860 12370,12879.39 12370,13095 ; 12447.3,13172.3 12370,13095 ; R20.7@13776,13186 13664,13186 13592,13258 12533,13258 12370,13095
D18: R20.8 U1.111 | length 1729.1
  Top Layer w8: U1.111@12449.03,12687.43 12449.03,12904.03 12789,13244 13551,13244 13659,13136 R20.8@13776,13136
D+: J1.3 R8.1 | length 721.6
  Top Layer w8: J1.3@9193.21,16450.37 9575.97,16450.37 R8.1@9815.6,16690
D-: J1.2 R7.1 | length 1074
  Top Layer w8: J1.2@9193.21,16371.63 9146,16418.84 9146,16672 9345,16871 R7.1@9817.6,16871
GND: A1.2 AT1.1 C1.1 C2.1 C3.1 C4.1 C5.1 C6.1 C7.1 C8.1 C9.1 C10.1 C11.1 C12.1 C13.1 C14.1 C15.1 C16.1 C17.2 C19.1 C20.1 C21.1 C22.2 C23.2 C24.2 C25.1 C26.1 C27.1 C28.1 C29.1 C30.1 C31.1 C32.1 C33.1 C34.1 C35.1 C36.1 C37.1 C38.1 C39.1 C40.1 C41.1 C42.2 C43.1 C44.1 C45.2 C46.1 C47.1 C48.2 C49.2 C50.1 C52.1 C53.1 D1.2 D2.2 D3.2 D4.2 D5.2 D6.2 D7.2 D8.2 D9.2 J1.4 L6.0 P1.1 P1.2 P2.6 P3.1 P3.2 P3.39 P3.40 P4.17 P4.18 P4.19 P4.20 P5.2 P5.10 PM2.4 PM2.5 R19.1 R22.1 RG2.5 RG2.6 RST.1 RST.2 S1.1 S15.1 SW1.3 SW1.4 SW2.3 SW2.4 SW3.3 SW3.4 SW5.9 SW5.10 SW5.11 SW5.12 SW5.13 SW5.14 SW5.15 SW5.16 SWdown.3 SWdown.4 SWP.1 SWup.3 SWup.4 U1.3 U1.4 U1.48 U1.56 U1.59 U1.68 U1.79 U1.95 U1.104 U1.112 U1.115 U1.121 U1.137 U1.142 U1.145 U2.5 U2.15 U2.23 U2.35 U2.43 U3.4 U4.A1 U4.A2 U5.5 U5.6 U5.7 U5.8 U6.4 U7.0 U7.6 U7.7 U7.8 U7.9 U7.10 U7.11 U7.27 U7.30 Y4.2 | length 487.5
  Top Layer w8: v1(11787,12942) 11815,12914 11815,12780 11838.8,12756.2 U1.142@11838.8,12687.43 ; v1@11937.22,12567.78 v1(11945,12560) ; U1.68@12409.66,11801.6 12409.66,11668.34 v1(12432,11646) ; U4.A1@13950,16634.37 AT1.1@13950,16670
  other v1: 11721,10308 9475,10315 13307,10348 9119,10576 10165,10635 8488,10673 14850,10780 14195,10840 12950,10875 13565,10875 8498,11067 10930,11075 11440,11085 9435,11180 14600,11205 14045,11220 13395,11230 12470,11325 12685,11350 11230,11355 11770,11365 12885,11380 14840,11415 13995,11635 9839,11675 13325,11685 11565,11690 11255,11760 13095,11760 12610,11775 12050,11910 11880,11915 12312,11916 9649,12016 13620,12020 10178,12043 10896,12058 12477,12143 9183,12157 8624,12160 12065.17,12165.77 12143.91,12165.77 12222.65,12165.77 9801,12170 12065.17,12244.51 12143.91,12244.51 12222.65,12244.51 11875,12270 12065.17,12323.25 12143.91,12323.25 12222.65,12323.25 9527,12346 12477,12408 11880,12435 13165,12450 13540,12450 12300,12560 12130,12565 13290,12685 13760,12685 12620,12695 10875,12700 10135,12745 11545,12780 10449,12788 9878,12858 14825,12885 14190,12930 13575,12955 10130,12980 12750,12985 11410,12990 13120,12995 10444,13005 12585,13105 9585,13134 10435,13267 10135,13280 9825,13298 9224,13378 12155,13425 12335,13425 14835,13515 12750,13540 11455,13545 12325,13575 9522,13583 10428,13596 10135,13610 13050,13670 13540,13673 13910,13680 14229,13694 11755,13760 12580,13800 12055,13880 8757,13884 10994,14089 10081,14100 11246,14104 8593,14117 10423,14198 10095,14333 11000,14351 11240,14354 10433,14399 13510,14405 14070,14415 12485,14425 13075,14427 12170,14470 14845,14560 10428,14566 10086,14570 8584,14579 13315,14590 13945,14595 9257,14758 13140,14785 13560,14785 8992,14823 14390,14890 14845,14925 12890,14935 14035,14940 10650,14950 13235,14975 11475,14995 11650,14995 12475,15015 13715,15105 8758,15140 11994,15143 10111,15157 13989,15198 12065,15205 14650,15205 9329,15228 10382,15228 13447,15228 11886,15232 12712,15251 13490,15298 9486,15310 11888,15377 9329,15404 10115,15406 13977,15416 12731,15442 12482,15448 10394,15449 14548,15468 14873,15562 10115,15563 12609,15578 10389,15607 14214,15694 13571,15700 11757,15791 12078,15832 14410,15874 9538,15890 13330,15911 10085,15967 14181,16001 13568,16015 11759,16030 12292,16031 10410,16077 13318,16089 12917,16094 10939,16095 12595,16095 11398,16097 8918,16155 14622,16169 9625,16323 10050,16395 8475,16400 14408,16407 13960,16445 14185,16540 10772,16585 9590,16776 10250,16785 10810,16790 12150,16790 12485,16815 13695,16846
  other v2: 8250,10250 14750,10250 8250,16750 14750,16750
H3: P3.3 U1.32 | length 1881
  Top Layer w8: P3.3@10787,10577 10735,10629 10735,11111 11602.76,11978.76 U1.32@11701,11978.76
H4: P3.4 U1.33 | length 1711.6
  Top Layer w8: P3.4@10787,10677 10787,11132 11614.08,11959.08 U1.33@11701,11959.08
H5: P3.5 U1.39 | length 1618.8
  Top Layer w8: P3.5@10887,10577 10940,10630 10940,10820 11838.8,11718.8 U1.39@11838.8,11801.6
H6: P3.6 U1.38 | length 1510.7
  Top Layer w8: P3.6@10887,10677 10887,10786.8 11819.11,11718.91 U1.38@11819.11,11801.6
H7: P3.7 U1.41 | length 1593.7
  Top Layer w8: P3.7@10987,10577 11037,10627 11037,10862 11878.17,11703.17 U1.41@11878.17,11801.6
H8: P3.8 U1.40 | length 1485.6
  Top Layer w8: P3.8@10987,10677 10987,10837 11858.48,11708.48 U1.40@11858.48,11801.6
H9: P3.9 U1.43 | length 1568.6
  Top Layer w8: P3.9@11087,10577 11138,10628 11138,10908 11917.54,11687.54 U1.43@11917.54,11801.6
H10: P3.10 U1.42 | length 1460.5
  Top Layer w8: P3.10@11087,10677 11087,10877 11897.85,11687.85 U1.42@11897.85,11801.6
H11: P3.11 U1.46 | length 1629.8
  Top Layer w8: P3.11@11187,10577 11238,10628 11238,10747 11777,11286 11855.99,11286 12015,11445.01 12015,11686.59 11976.59,11725 U1.46@11976.59,11801.6
H12: P3.12 U1.44 | length 1435.4
  Top Layer w8: P3.12@11187,10677 11187,10937 11937.22,11687.22 U1.44@11937.22,11801.6
H13: P3.13 U1.50 | length 1542.9
  Top Layer w8: P3.13@11287,10577 11335,10625 11335,10725.41 12055.33,11445.74 U1.50@12055.33,11801.6
H14: P3.14 U1.49 | length 1465.6
  Top Layer w8: P3.14@11287,10677 11287,10750 11809,11272 11861.79,11272 12035.65,11445.85 U1.49@12035.65,11801.6
H15: P3.15 U1.52 | length 1517.7
  Top Layer w8: P3.15@11387,10577 11436,10626 11436,10753 12094.7,11411.7 U1.52@12094.7,11801.6
H16: P3.16 U1.51 | length 1409.6
  Top Layer w8: P3.16@11387,10677 11387,10757.61 12075.02,11445.62 U1.51@12075.02,11801.6
H17: P3.17 U1.55 | length 1500.8
  Top Layer w8: P3.17@11487,10577 11532,10622 11532,10805.2 12153.76,11426.96 U1.55@12153.76,11801.6
H18: P3.18 U1.53 | length 1384.5
  Top Layer w8: P3.18@11487,10677 11487,10780 12114.39,11407.39 U1.53@12114.39,11801.6
H19: P3.19 U1.58 | length 1483.8
  Top Layer w8: P3.19@11587,10577 11640,10630 11640,10732 12212.81,11304.81 U1.58@12212.81,11801.6
H20: P3.20 U1.57 | length 1375.7
  Top Layer w8: P3.20@11587,10677 11587,10748 12193.13,11354.13 U1.57@12193.13,11801.6
H21: P3.21 U1.61 | length 1466.9
  Top Layer w8: P3.21@11687,10577 11739,10629 11739,10722 12250,11233 12250,11665.2 12271.87,11687.07 U1.61@12271.87,11801.6
H22: P3.22 U1.60 | length 1358.7
  Top Layer w8: P3.22@11687,10677 11687,10731 12235,11279 12235,11670 12252.18,11687.18 U1.60@12252.18,11801.6
H23: P3.23 U1.63 | length 1441.7
  Top Layer w8: P3.23@11787,10577 11841,10631 11841,10750 12291.55,11200.55 12291.55,11616.55 12311.24,11636.24 U1.63@12311.24,11801.6
H24: P3.24 U1.62 | length 1333.6
  Top Layer w8: P3.24@11787,10677 11787,10744 12264,11221 12264,11640 12291.55,11667.55 U1.62@12291.55,11801.6
H25: P3.25 U1.65 | length 1416.6
  Top Layer w8: P3.25@11887,10577 11938,10628 11938,10733 12320,11115 12320,11580.8 12350.61,11611.4 U1.65@12350.61,11801.6
H26: P3.26 U1.64 | length 1308.5
  Top Layer w8: P3.26@11887,10677 11887,10772 12306,11191 12306,11586.6 12330.92,11611.52 U1.64@12330.92,11801.6
H27: P3.27 U1.69 | length 1545.9
  Top Layer w8: P3.27@11987,10577 11987,10584 12038,10635 12038,10714 12596,11272 12596,11539 12429.35,11705.65 U1.69@12429.35,11801.6
H28: P3.28 U1.66 | length 1283.4
  Top Layer w8: P3.28@11987,10677 11987,10723 12334,11070 12334,11575 12370.29,11611.29 U1.66@12370.29,11801.6
H29: P3.29 U1.74 | length 1776.9
  Top Layer w8: P3.29@12087,10577 12140,10630 12140,10704 12762.1,11326.1 12762.1,11884.3 12726.7,11919.71 U1.74@12586.83,11919.71
H30: P3.30 U1.70 | length 1407.9
  Top Layer w8: P3.30@12087,10677 12087,10707 12610,11230 12610,11565 12449.03,11725.97 U1.70@12449.03,11801.6
H31: P3.31 U1.76 | length 1803.9
  Top Layer w8: P3.31@12187,10577 12240,10630 12240,10709 12797,11266 12797,11889.01 12726.93,11959.08 U1.76@12586.83,11959.08
H32: P3.32 U1.75 | length 1666.8
  Top Layer w8: P3.32@12187,10677 12776.1,11266.1 12776.1,11890.1 12726.81,11939.4 U1.75@12586.83,11939.4
H33: P3.33 U1.80 | length 2035
  Top Layer w8: P3.33@12287,10577 12339,10629 12339,10718 12960,11339 12960,11905 12827.18,12037.82 U1.80@12586.83,12037.82
H34: P3.34 U1.77 | length 1693.8
  Top Layer w8: P3.34@12287,10677 12287,10685.8 12811,11209.8 12811,11894.8 12727.04,11978.76 U1.77@12586.83,11978.76
H35: P3.35 U1.82 | length 2068.2
  Top Layer w8: P3.35@12387,10577 12438,10628 12438,10703 12853,11118 12853,11192.4 12988,11327.4 12988,11937 12847.81,12077.19 U1.82@12586.83,12077.19
H36: P3.36 U1.81 | length 1930.9
  Top Layer w8: P3.36@12387,10677 12839,11129 12839,11198.2 12974,11333.2 12974,11921 12837.5,12057.5 U1.81@12586.83,12057.5
H37: P3.37 U1.84 | length 2187.6
  Top Layer w8: P3.37@12487,10577 12544,10634 12544,10707 13026,11189 13026,12092 13001.44,12116.56 U1.84@12586.83,12116.56
H38: P3.38 U1.83 | length 1964.1
  Top Layer w8: P3.38@12487,10677 12867,11057 12867,11186.6 13002,11321.6 13002,11953 12858.12,12096.88 U1.83@12586.83,12096.88
H\O\L\D\: U2.1 U6.7 | length 2706.6
  Top Layer w8: U2.1@12222.44,15097.52 12539.48,15097.52 12762,14875 14250,14875 14540,15165 14540,15250 14518,15272 U6.7@14457.4,15272
HT1: P4.1 U1.89 | length 2284.7
  Top Layer w8: U1.89@12586.83,12214.99 13630.01,12214.99 14104,11741 14497,11741 P4.1@14623,11867
HT2: P4.2 U1.90 | length 2088.5
  Top Layer w8: U1.90@12586.83,12234.67 13700.33,12234.67 14068,11867 P4.2@14523,11867
HT3: P4.3 U1.91 | length 2195
  Top Layer w8: U1.91@12586.83,12254.35 13762.65,12254.35 14098,11919 14575,11919 P4.3@14623,11967
HT4: P4.4 U1.92 | length 2063.4
  Top Layer w8: U1.92@12586.83,12274.04 13814.96,12274.04 14122,11967 P4.4@14523,11967
HT5: P4.5 U1.93 | length 2169.9
  Top Layer w8: U1.93@12586.83,12293.73 13848.27,12293.73 14123,12019 14575,12019 P4.5@14623,12067
HT6: P4.6 U1.96 | length 2054.5
  Top Layer w8: U1.96@12586.83,12352.78 12784.22,12352.78 12829.27,12307.73 13899.27,12307.73 14140,12067 P4.6@14523,12067
HT7: P4.7 U1.97 | length 2159.4
  Top Layer w8: U1.97@12586.83,12372.47 12784.33,12372.47 12835.07,12321.73 13939.27,12321.73 14140,12121 14577,12121 P4.7@14623,12167
HT8: P4.8 U1.98 | length 2029.4
  Top Layer w8: U1.98@12586.83,12392.15 12784.45,12392.15 12840.87,12335.73 13974.27,12335.73 14143,12167 P4.8@14523,12167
